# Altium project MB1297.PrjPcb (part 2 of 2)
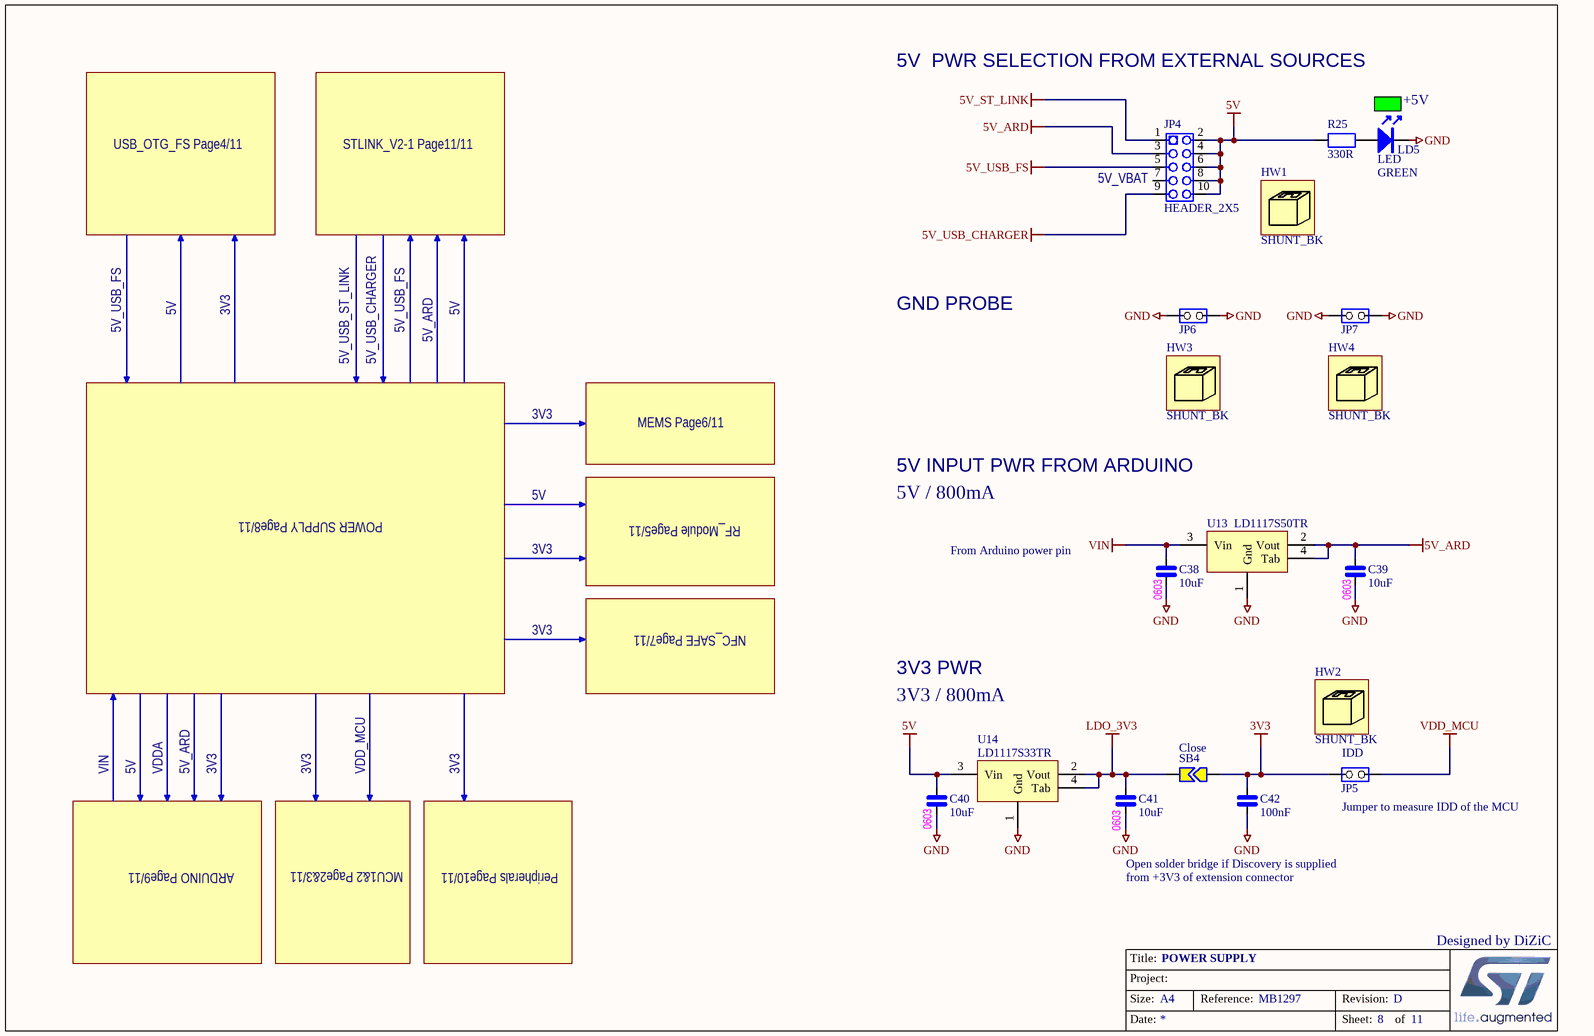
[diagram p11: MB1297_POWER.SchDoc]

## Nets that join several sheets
3V3: MB1297_MCU1 (R8.1 R9.1 R10.1 R11.1), MB1297_RF_Module (7 pins), MB1297_Peripherals (6 pins), MB1297_NFC_SAFE (C33.1 L2.2 R4.1 U9.2), MB1297_Arduino (CN2.2 CN2.4), MB1297_MEMS (37 pins), MB1297_USB_OTG_FS (LD8.A LD9.A R58.1 R62.1), MB1297_POWER (C42.1 JP5.1 SB4.2)
5V: MB1297_RF_Module (C49.1 U12.1), MB1297_STLINK_V2-1 (D2.1), MB1297_Arduino (CN2.5), MB1297_USB_OTG_FS (U19.5), MB1297_POWER (8 pins)
5V_ARD: MB1297_STLINK_V2-1 (D3.1), MB1297_Arduino (R3.1), MB1297_POWER (C39.1 JP4.3 U13.2 U13.4)
5V_ST_LINK: MB1297_STLINK_V2-1 (C65.1 SB11.1 U17.6 U17.7), MB1297_POWER (JP4.1)
5V_USB_CHARGER: MB1297_STLINK_V2-1 (11 pins), MB1297_POWER (JP4.9)
5V_USB_FS: MB1297_STLINK_V2-1 (D5.1), MB1297_USB_OTG_FS (R61.1), MB1297_POWER (JP4.5)
GND: MB1297_MCU1 (C14.2 C15.2), MB1297_MCU2 (20 pins), MB1297_RF_Module (29 pins), MB1297_Peripherals (14 pins), MB1297_NFC_SAFE (11 pins), MB1297_STLINK_V2-1 (42 pins), MB1297_Arduino (C1.2 CN1.7 CN2.6 CN2.7), MB1297_MEMS (36 pins), MB1297_USB_OTG_FS (11 pins), MB1297_POWER (12 pins)
VDD_MCU: MB1297_MCU2 (15 pins), MB1297_POWER (JP5.2)
VDDA: MB1297_MCU2 (5 pins), MB1297_Arduino (C1.1 R2.2)
VIN: MB1297_Arduino (CN2.8), MB1297_POWER (C38.1 U13.3)
NetC3_2: MB1297_MCU2 (C3.2 U1.14), MB1297_Peripherals (SB2.1), MB1297_STLINK_V2-1 (R34.2 SB8.1), MB1297_Arduino (CN2.3)
NetC66_1: MB1297_MCU1 (U1.68), MB1297_USB_OTG_FS (6 pins)
NetCN1_1: MB1297_MCU1 (U1.37), MB1297_Arduino (CN1.1)
NetCN1_2: MB1297_MCU1 (U1.77), MB1297_Arduino (CN1.2)
NetCN1_3: MB1297_MCU1 (U1.25), MB1297_Arduino (CN1.3)
NetCN1_4: MB1297_MCU1 (U1.32), MB1297_Arduino (CN1.4)
NetCN1_5: MB1297_MCU1 (U1.31), MB1297_Arduino (CN1.5)
NetCN1_6: MB1297_MCU1 (U1.30), MB1297_Peripherals (SB1.1), MB1297_Arduino (CN1.6)
NetCN1_9: MB1297_MCU1 (R8.2 U1.96), MB1297_Arduino (CN1.9)
NetCN1_10: MB1297_MCU1 (R9.2 U1.95), MB1297_Arduino (CN1.10)
NetCN3_1: MB1297_MCU1 (U1.24), MB1297_Arduino (CN3.1)
NetCN3_2: MB1297_MCU1 (U1.23), MB1297_Arduino (CN3.2)
NetCN3_3: MB1297_MCU1 (U1.61), MB1297_Arduino (CN3.3)
NetCN3_4: MB1297_MCU1 (U1.35), MB1297_Arduino (CN3.4)
NetCN3_5: MB1297_MCU1 (U1.26), MB1297_Arduino (CN3.5)
NetCN3_6: MB1297_MCU1 (U1.90), MB1297_Arduino (CN3.6)
NetCN3_7: MB1297_MCU1 (U1.36), MB1297_Arduino (CN3.7)
NetCN3_8: MB1297_MCU1 (U1.29), MB1297_Arduino (CN3.8)
NetCN4_1: MB1297_MCU1 (U1.34), MB1297_Arduino (CN4.1)
NetCN4_2: MB1297_MCU1 (U1.33), MB1297_Arduino (CN4.2)
NetCN4_3: MB1297_MCU1 (U1.18), MB1297_Arduino (CN4.3)
NetCN4_4: MB1297_MCU1 (U1.17), MB1297_Arduino (CN4.4)
NetCN4_5: MB1297_MCU1 (U1.16), MB1297_Arduino (CN4.5)
NetCN4_6: MB1297_MCU1 (U1.15), MB1297_Arduino (CN4.6)
NetCN9_4: MB1297_MCU1 (U1.69), MB1297_USB_OTG_FS (CN9.4 U20.A3)
NetCN10_7: MB1297_MCU1 (U1.83), MB1297_Peripherals (CN10.7)
NetCN10_8: MB1297_MCU1 (U1.81), MB1297_Peripherals (CN10.8)
NetM1_4: MB1297_MCU1 (U1.5), MB1297_RF_Module (M1.4)
NetM1_7: MB1297_MCU1 (U1.78), MB1297_RF_Module (M1.7 M2.11 M3.7)
NetM1_8: MB1297_MCU1 (U1.79), MB1297_RF_Module (M1.8 M2.10 M3.8)
NetM1_9: MB1297_MCU1 (U1.80), MB1297_RF_Module (M1.9 M2.9 M3.9)
NetM1_10: MB1297_MCU1 (U1.60), MB1297_RF_Module (M1.10)
NetM1_11: MB1297_MCU1 (U1.67), MB1297_RF_Module (M1.11)
NetM2_12: MB1297_MCU1 (U1.97), MB1297_RF_Module (M2.12 R26.1)
NetM2_13: MB1297_MCU1 (U1.98), MB1297_RF_Module (M2.13)
NetM2_16: MB1297_MCU1 (U1.52), MB1297_RF_Module (M2.16)
NetM2_21: MB1297_MCU1 (U1.55), MB1297_RF_Module (M2.21)
NetM2_22: MB1297_MCU1 (U1.56), MB1297_RF_Module (M2.22)
NetM2_33: MB1297_MCU1 (U1.51), MB1297_RF_Module (M2.33)
NetM2_34: MB1297_MCU1 (U1.39), MB1297_RF_Module (M2.34)
NetM3_1: MB1297_MCU1 (U1.4), MB1297_RF_Module (M3.1)
NetM3_10: MB1297_MCU1 (U1.91), MB1297_RF_Module (M3.10)
NetM3_11: MB1297_MCU1 (U1.54), MB1297_RF_Module (M3.11)
NetR1_2: MB1297_MCU1 (U1.1), MB1297_NFC_SAFE (R1.2 U8.1)
NetR4_2: MB1297_MCU1 (U1.3), MB1297_NFC_SAFE (R4.2 U8.7)
NetR6_2: MB1297_MCU1 (U1.40), MB1297_MEMS (R6.2)
NetR10_2: MB1297_MCU1 (R10.2 U1.47), MB1297_NFC_SAFE (U8.6 U9.7), MB1297_MEMS (5 pins)
NetR11_2: MB1297_MCU1 (R11.2 U1.48), MB1297_NFC_SAFE (U8.5 U9.5), MB1297_MEMS (5 pins)
NetR13_2: MB1297_MCU1 (U1.38), MB1297_MEMS (R13.2)
NetR14_2: MB1297_MCU1 (U1.64), MB1297_MEMS (R14.2 U4.7)
NetR15_2: MB1297_MCU1 (U1.63), MB1297_MEMS (R15.2 U4.5)
NetR20_1: MB1297_MCU1 (U1.53), MB1297_Peripherals (R20.1)
NetR21_1: MB1297_MCU1 (U1.66), MB1297_Peripherals (R21.1 R22.1)
NetR32_2: MB1297_MCU1 (U1.76), MB1297_STLINK_V2-1 (R32.2 SB6.1)
NetR33_2: MB1297_MCU1 (U1.72), MB1297_STLINK_V2-1 (R33.2 SB5.1)
NetR35_2: MB1297_MCU1 (U1.89), MB1297_STLINK_V2-1 (R35.2 SB7.1)
NetR42_2: MB1297_MCU1 (U1.93), MB1297_STLINK_V2-1 (R42.2)
NetR43_2: MB1297_MCU1 (U1.92), MB1297_STLINK_V2-1 (R43.2)
NetR56_1: MB1297_MCU1 (U1.2), MB1297_USB_OTG_FS (R56.1 R58.2 U19.3)
NetR62_2: MB1297_MCU1 (U1.59), MB1297_USB_OTG_FS (R62.2 U19.4)
NetSB3_1: MB1297_MCU1 (U1.7), MB1297_Peripherals (SB3.1)
NetSB12_2: MB1297_MCU1 (U1.86), MB1297_Peripherals (SB12.2 SB14.2)
NetSB15_2: MB1297_MCU1 (U1.85), MB1297_Peripherals (SB15.2 SB16.2)
NetSB18_2: MB1297_MCU1 (U1.84), MB1297_Peripherals (SB18.2 SB19.2)
NetSB20_1: MB1297_MCU1 (U1.87), MB1297_Peripherals (SB20.1)
NetSB21_1: MB1297_MCU1 (U1.82), MB1297_Peripherals (SB21.1)
NetU1_41: MB1297_MCU1 (U1.41), MB1297_RF_Module (U11.6)
NetU1_42: MB1297_MCU1 (U1.42), MB1297_RF_Module (U11.1)
NetU1_43: MB1297_MCU1 (U1.43), MB1297_RF_Module (U11.5)
NetU1_44: MB1297_MCU1 (U1.44), MB1297_RF_Module (U11.2)
NetU1_45: MB1297_MCU1 (U1.45), MB1297_RF_Module (U11.3)
NetU1_46: MB1297_MCU1 (U1.46), MB1297_RF_Module (U11.7)
NetU1_57: MB1297_MCU1 (U1.57), MB1297_MEMS (U7.7)
NetU1_58: MB1297_MCU1 (U1.58), MB1297_MEMS (U3.4)
NetU1_62: MB1297_MCU1 (U1.62), MB1297_MEMS (U6.3)
NetU1_65: MB1297_MCU1 (U1.65), MB1297_MEMS (U5.8)
NetU1_88: MB1297_MCU1 (U1.88), MB1297_NFC_SAFE (U9.1)
USB_N: MB1297_MCU1 (U1.70), MB1297_USB_OTG_FS (CN9.2 U20.D1 U20.D3)
USB_P: MB1297_MCU1 (U1.71), MB1297_USB_OTG_FS (CN9.3 U20.C1 U20.C3)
